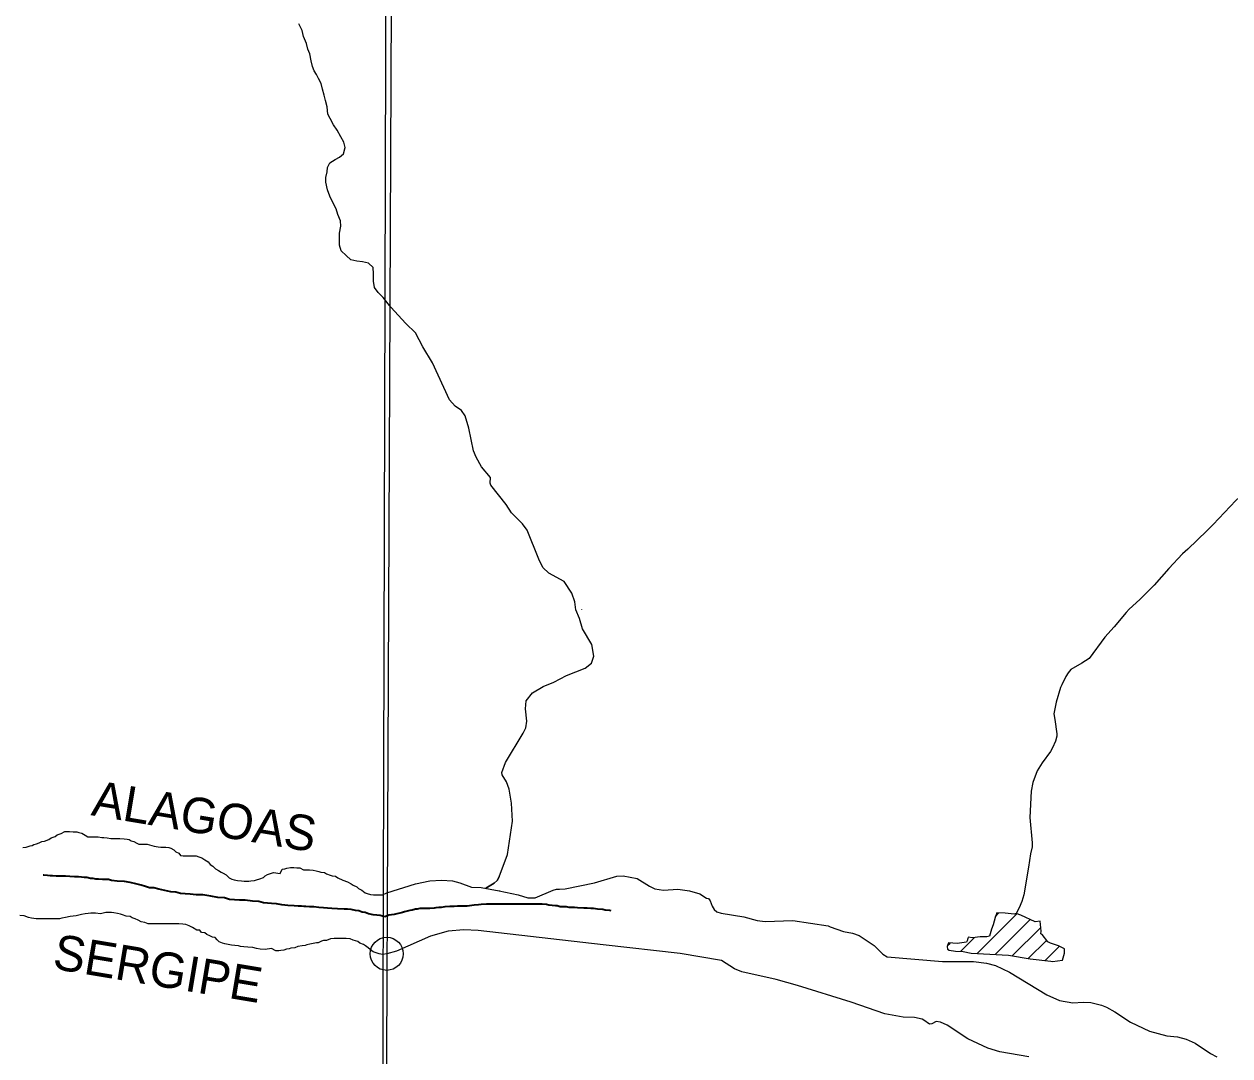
# Model space of a CAD drawing. Extents: x 553962 to 842807, y 8883888 to 9032388.
# Drawn here: x 595747 to 598478, y 8904160 to 8906496 of the extents above; entities that cross this region are included whole.
import ezdxf
from ezdxf.enums import TextEntityAlignment as Align

# ---------------------------------------------------------------- set-up
doc = ezdxf.new("R2010")
doc.units = 0
doc.header["$LTSCALE"] = 150
doc.header["$PDMODE"] = 32
doc.header["$PDSIZE"] = 75
doc.linetypes.add('LONG_DASH_SHORT_DASH', pattern=[9.9, 6, -1.2, 1.5, -1.2])
doc.layers.add('6', color=7, linetype='Continuous', lineweight=13)

msp = doc.modelspace()

# ---------------------------------------------------------------- linework, layer by layer
at = {"layer": '6'}
for p, q in [((597009.3, 8905170.6), (597009.5, 8905170.5)), ((597905.6, 8904392.3), (597995.3, 8904482)), ((597945.7, 8904390), (598025, 8904469.3)), ((597946.4, 8904475.5), (597954.7, 8904483.9)), ((597984.9, 8904386.8), (598049.1, 8904451)), ((597838.3, 8904409.9), (597844.2, 8904415.7)), ((597867.6, 8904396.8), (597899.4, 8904428.5)), ((598021.1, 8904380.5), (598062.5, 8904421.9)), ((598059, 8904376), (598091.6, 8904408.6))]:
    msp.add_line(p, q, dxfattribs=at)
for points in [[(596655.5, 8924715.8), (596593.3, 8909930.3), (596531.7, 8896026.7)], [(596461.2, 8906005.4), (596461.2, 8906022.7), (596463.8, 8906039.2), (596463.4, 8906051.2), (596457.4, 8906065.3), (596453.5, 8906078.3), (596444.6, 8906095.4), (596439.1, 8906106.9), (596433.7, 8906120.9), (596429.8, 8906138.5), (596429.8, 8906149), (596432.9, 8906162), (596433.9, 8906171.5), (596439.5, 8906182), (596451, 8906189.9), (596461, 8906195.4), (596470.1, 8906202.3), (596474.2, 8906216.8), (596471.2, 8906229.4), (596464.2, 8906241.4), (596455.8, 8906256), (596447.9, 8906268), (596439.9, 8906282.6), (596434.5, 8906292.6), (596433, 8906308.7), (596429.1, 8906323.7), (596426.2, 8906335.2), (596422.7, 8906348.8), (596419.3, 8906361.8), (596413.8, 8906373.3), (596408.8, 8906382.4), (596403.4, 8906390.9), (596399.9, 8906400.4), (596397, 8906413.4), (596393.6, 8906429), (596389.6, 8906440), (596386.2, 8906452.6), (596379.7, 8906468.6), (596376.3, 8906481.6), (596368.8, 8906497.2)], [(596838.8, 8905408.9), (596804, 8905452.2), (596802.6, 8905456.8), (596803.3, 8905469.9), (596782.8, 8905493.9), (596770.6, 8905515.5), (596764.7, 8905530.2), (596754.3, 8905581.4), (596745.9, 8905609.6), (596737.4, 8905621.2), (596722.8, 8905631.7), (596710.6, 8905646), (596672.1, 8905729.1), (596650.2, 8905765.8), (596633.6, 8905797.4), (596611.2, 8905818.6), (596577.4, 8905855.5), (596559.7, 8905877.5), (596548.7, 8905888.6), (596540.2, 8905900.2), (596538.3, 8905914.2), (596537.9, 8905930.7), (596537.5, 8905945.2), (596527, 8905955.3), (596513.5, 8905957.9), (596500.5, 8905959.4), (596487, 8905962.5), (596476, 8905972.6), (596464.6, 8905983.1), (596461.1, 8905995.7), (596461.2, 8906005.4)], [(596792.7, 8904540.1), (596811.4, 8904551.1), (596818.4, 8904557.4), (596822.7, 8904565.5), (596841.5, 8904615.9), (596853.2, 8904691.8), (596850.7, 8904732.7), (596845.1, 8904764.5), (596839.3, 8904781), (596829.4, 8904796.5), (596828.9, 8904802.2), (596837.1, 8904824.7), (596877.1, 8904890.7), (596882.8, 8904903.4), (596885.5, 8904918), (596882.5, 8904946.3), (596884.2, 8904964.5), (596897.9, 8904982), (596922.6, 8904996.6), (596946.5, 8905006.2), (596975.3, 8905021.5), (597017.5, 8905037.8), (597031.8, 8905049.4), (597037, 8905065), (597032.3, 8905091.9), (597011.4, 8905127.4), (597004.9, 8905150.7), (596996.7, 8905170.4), (596994.1, 8905188.6), (596987.3, 8905208), (596969.8, 8905234), (596935.4, 8905253.2), (596921.5, 8905266.1), (596912.2, 8905285.1), (596886, 8905350.5), (596875.4, 8905364.7), (596850.4, 8905390), (596838.8, 8905408.9)], [(595744.1, 8904632.1), (595751.7, 8904633.1), (595756.2, 8904634.6), (595760.7, 8904636), (595765.2, 8904637), (595769.2, 8904639), (595774.7, 8904640.4), (595781.2, 8904642.4), (595786.8, 8904645.4), (595793.3, 8904646.3), (595802.8, 8904650.3), (595807.8, 8904653.7), (595816.9, 8904657.2), (595821.4, 8904660.7), (595830.4, 8904663.6), (595839, 8904668.1), (595845, 8904668), (595850, 8904668), (595858, 8904667.9), (595866, 8904667.4), (595870.5, 8904665.8), (595877.5, 8904664.8), (595884.9, 8904659.7), (595891.4, 8904656.2), (595899.4, 8904656.1), (595903.4, 8904656.1), (595910.9, 8904656.1), (595914.9, 8904656), (595922.9, 8904655), (595927.4, 8904654.4), (595934.9, 8904653.9), (595943.4, 8904652.3), (595951.4, 8904652.3), (595956.4, 8904652.3), (595963.4, 8904652.2), (595973.4, 8904651.6), (595980.4, 8904651.1), (595984.9, 8904650.6), (595989.4, 8904647.5), (595995.3, 8904646), (596002.3, 8904641.9), (596006.8, 8904639.9), (596012.8, 8904639.9), (596025.8, 8904639.8), (596041.3, 8904635.2), (596045.8, 8904634.6), (596050.3, 8904633.6), (596056.3, 8904633.1), (596063.8, 8904633), (596067.8, 8904633), (596074.3, 8904632.4), (596079.3, 8904630.4), (596086.2, 8904626.9), (596090.2, 8904622.3), (596097.2, 8904619.3), (596100.7, 8904614.2), (596107.2, 8904613.2), (596113.7, 8904613.2), (596120.7, 8904613.1), (596124.7, 8904613.1), (596128.7, 8904613.1), (596136.2, 8904613), (596142.2, 8904611), (596149.6, 8904608.4), (596156.1, 8904604.4), (596163.6, 8904599.3), (596168, 8904593.3), (596174.5, 8904590.2), (596180.5, 8904583.7), (596186.9, 8904580.1), (596193.4, 8904576.1), (596197.9, 8904574.1), (596204.4, 8904570), (596211.3, 8904563.4), (596217.3, 8904560.4), (596222.8, 8904558.9), (596229.8, 8904557.3), (596238.8, 8904556.3), (596245.3, 8904556.2), (596249.3, 8904556.2), (596255.8, 8904556.1), (596260.3, 8904556.6), (596268.3, 8904557.6), (596272.8, 8904559), (596280.8, 8904561), (596288.9, 8904564.4), (596292.9, 8904567.9), (596298.4, 8904570.9), (596307, 8904574.3), (596312, 8904575.3), (596327, 8904573.2), (596331.5, 8904582.7), (596337.5, 8904584.1)], [(596337.5, 8904584.1), (596341.6, 8904585.6), (596350.1, 8904586.6), (596357.6, 8904586.5), (596364.6, 8904586), (596371.1, 8904585.9), (596379.5, 8904581.9), (596386.5, 8904581.3), (596393.5, 8904581.3), (596401.5, 8904580.7), (596408, 8904579.2), (596414, 8904578.1), (596419, 8904576.6), (596427, 8904575.5), (596432, 8904572.5), (596440, 8904569.4), (596444.5, 8904567.9), (596452, 8904566.9), (596457.4, 8904563.3), (596468.4, 8904558.2), (596478.9, 8904554.7), (596487.3, 8904550.1), (596492.3, 8904546.6), (596500.3, 8904543), (596504.3, 8904539), (596511.7, 8904535.4), (596519.2, 8904529.4), (596523.7, 8904527.8), (596531.7, 8904525.8), (596538.2, 8904524.7), (596545.2, 8904524.7), (596549.2, 8904524.7), (596554.2, 8904525.1), (596558.2, 8904525.1), (596568.1, 8904529.4), (596633, 8904549.7), (596665.5, 8904556.5), (596692.3, 8904558.4), (596717.2, 8904557), (596733.8, 8904552.4)], [(596733.8, 8904552.4), (596760.4, 8904542.1), (596781.9, 8904541.7), (596822.9, 8904534.3)], [(596822.7, 8904565.5), (596818.4, 8904557.4), (596811.4, 8904551.1), (596792.7, 8904540.1)], [(596823.3, 8904534.6), (596822.9, 8904534.3), (596866.1, 8904524.6), (596887.5, 8904518.1), (596904.4, 8904518.5), (596944.7, 8904535.2), (596952.2, 8904537.4), (596959.2, 8904537.7), (596972.2, 8904538.7), (597038.5, 8904552.3), (597088.9, 8904566.9), (597103.5, 8904567.8), (597135.1, 8904562.2), (597163.3, 8904544.4), (597175.5, 8904538.6), (597195.2, 8904535.8), (597227.3, 8904537.4), (597253.9, 8904534.1), (597277.1, 8904527.3), (597291.9, 8904517.4), (597296.9, 8904516.7), (597300.6, 8904511.3), (597305.1, 8904499.1), (597310, 8904491.8), (597315.9, 8904486.6), (597325.4, 8904483.2), (597377.2, 8904474.8), (597406.8, 8904466.6), (597425.4, 8904464.6), (597488, 8904467), (597567.9, 8904454.9)], [(596113, 8904457.9), (596106, 8904458.5), (596097.5, 8904459.1), (596092.5, 8904459.1), (596084.5, 8904459.1), (596079.5, 8904459.2), (596067.5, 8904459.2), (596057, 8904459.3), (596050, 8904459.4), (596042, 8904459.4), (596036.5, 8904459.5), (596028, 8904459.5), (596020, 8904462.6), (596012, 8904463.6), (596005, 8904467.7), (595998.5, 8904470.7), (595991.5, 8904472.8), (595987.1, 8904475.8), (595977.6, 8904476.9), (595969.6, 8904479.9), (595965.1, 8904481.5), (595958.6, 8904482.5), (595950.1, 8904484.1), (595945.1, 8904485.1), (595936.6, 8904485.2), (595932.1, 8904485.2), (595920.1, 8904482.3), (595908.6, 8904483.3), (595897.6, 8904483.4), (595892.1, 8904482.9), (595885.1, 8904482), (595877, 8904480.5), (595865, 8904477.1), (595851, 8904476.2), (595840.5, 8904473.3), (595832.5, 8904471.8), (595827, 8904470.9), (595816.4, 8904470.4), (595808.4, 8904470.5), (595798.4, 8904470.5), (595789.4, 8904470.6), (595783.9, 8904470.6), (595773.9, 8904470.7), (595763.9, 8904472.3), (595756.9, 8904473.8), (595747, 8904477.4), (595737, 8904478)], [(596137.9, 8904445.3), (596128.4, 8904450.8), (596120.5, 8904454.9), (596113, 8904457.9)], [(596412.8, 8904415.9), (596408.8, 8904415.9), (596401.3, 8904414.5), (596394.3, 8904413), (596387.2, 8904411.6), (596383.2, 8904410.6), (596376.2, 8904409.6), (596366.7, 8904408.2), (596360.2, 8904405.2), (596351.2, 8904404.3), (596347.2, 8904402.8), (596341.2, 8904401.9), (596335.1, 8904399.9), (596328.6, 8904398.9), (596324.1, 8904398.5), (596317.1, 8904398.5), (596307.2, 8904403.6), (596293.1, 8904401.2), (596281.1, 8904402.3), (596273.1, 8904403.8), (596264.6, 8904405.4), (596253.7, 8904406.4), (596244.7, 8904407.5), (596236.7, 8904408.1), (596232.2, 8904409.1), (596224.2, 8904410.2), (596216.7, 8904411.2), (596208.7, 8904412.8), (596201.2, 8904414.3), (596196.2, 8904415.8), (596188.7, 8904418.9), (596184.2, 8904422.9), (596179.3, 8904428), (596173.3, 8904429), (596167.8, 8904432.1), (596160.3, 8904435.1), (596155.8, 8904438.6), (596148.8, 8904439.7), (596144.9, 8904444.7), (596137.9, 8904445.3)], [(597784.5, 8904240.9), (597780.8, 8904243.5), (597763, 8904246.9), (597737.7, 8904248), (597696.4, 8904255.7), (597619.9, 8904282.1), (597498.2, 8904319.6), (597450, 8904332.9), (597372.6, 8904350.3), (597356, 8904357.7), (597326.5, 8904376.3), (597232.9, 8904391.8), (597058.1, 8904411.6), (596775.1, 8904444.1), (596742.4, 8904446), (596707.5, 8904442.8), (596667.4, 8904431.6), (596590.1, 8904397.6), (596568.1, 8904391.5), (596558.7, 8904389.9), (596551.2, 8904391.5), (596544.2, 8904394), (596537.7, 8904395.6), (596530.7, 8904401.1), (596526.2, 8904404.6), (596520.3, 8904409.2), (596515.8, 8904412.2), (596506.8, 8904415.8), (596502.3, 8904419.3), (596492.4, 8904422.4), (596485.4, 8904425.4), (596475.9, 8904426), (596467.4, 8904426.1), (596458.4, 8904426.1), (596449.4, 8904426.2), (596440.4, 8904425.2), (596431.8, 8904421.3), (596424.8, 8904421.3), (596420.3, 8904419.9), (596412.8, 8904415.9)], [(597567.9, 8904454.9), (597572.2, 8904452.6), (597602.6, 8904441.6), (597622.9, 8904438.2), (597638, 8904432.9), (597672.2, 8904410.2), (597691.4, 8904390.6), (597701.7, 8904384.3), (597826.9, 8904374.3), (597896.6, 8904373.8), (597926.2, 8904370), (597946.7, 8904364.9), (597978.4, 8904349.8), (598062.8, 8904298.6), (598092.1, 8904285.4), (598121.7, 8904280.6), (598145.7, 8904281.8), (598162.6, 8904280.9), (598187.1, 8904274.8), (598198.3, 8904270.4), (598217.2, 8904259.9), (598252.8, 8904236.5), (598295.7, 8904216.1), (598334.6, 8904205.9), (598358.9, 8904203.3), (598378.5, 8904198.1), (598398.6, 8904189.3), (598434, 8904165.6), (598448.2, 8904158.3)], [(598021.9, 8904158.5), (597956.3, 8904169.2), (597929.3, 8904177.5), (597883.8, 8904198.6), (597837.6, 8904229.6), (597822.4, 8904236.9), (597812.2, 8904237.9), (597802.9, 8904232.5), (597797.6, 8904231.9), (597784.5, 8904240.9)]]:
    msp.add_lwpolyline(points, dxfattribs=at)
for points in [[(596575.8, 8909932.4), (585614.8, 8909969.8), (585583.8, 8898914.4), (596544.8, 8898874.9)], [(598076.1, 8904374.3), (598098.6, 8904377.3), (598102.8, 8904393.2), (598103.1, 8904402.4), (598089.5, 8904409.8), (598071, 8904415.8), (598065, 8904418.6), (598052.1, 8904435.2), (598049.2, 8904436.8), (598050, 8904442.7), (598047.6, 8904465), (598036.8, 8904463.8), (598004.4, 8904478.8), (597993.7, 8904482.5), (597989.2, 8904480.8), (597968.7, 8904483.6), (597949.6, 8904484), (597945.8, 8904474), (597941.6, 8904457.1), (597937.6, 8904447), (597933.3, 8904431.5), (597927.5, 8904429.7), (597912, 8904430), (597894.4, 8904427.9), (597885.2, 8904428.9), (597883.8, 8904426.4), (597882.9, 8904420.8), (597881.3, 8904418.1), (597859.9, 8904414.8), (597840.3, 8904416), (597837.6, 8904407.7), (597838.4, 8904401.7), (597841.9, 8904400), (597856, 8904397.5), (597873.8, 8904396.3), (597891.4, 8904393.1), (597976.5, 8904388.3), (598025.4, 8904379.8), (598072.1, 8904374.5)]]:
    msp.add_lwpolyline(points, close=True, dxfattribs=at)
at = {"layer": '6', "lineweight": 25}
for points in [[(598811.5, 8905757.4), (598733.5, 8905676.3), (598498.6, 8905424.2), (598490.9, 8905418), (598439.8, 8905363.3), (598425.4, 8905349.3)], [(598425.4, 8905349.3), (598382.1, 8905307.4), (598370, 8905296.7), (598339.1, 8905264), (598305.9, 8905226), (598273.9, 8905193.3), (598249.7, 8905171.9), (598243, 8905164.1)], [(598243, 8905164.1), (598215.7, 8905131.8), (598194.5, 8905108.4), (598159.2, 8905060.4), (598142.4, 8905049.3), (598117.3, 8905035), (598111.1, 8905027.6), (598105.9, 8905019.5), (598097.1, 8905000.6)], [(598097.1, 8905000.6), (598094.2, 8904994.3), (598084, 8904960.9), (598079.1, 8904934.7), (598081, 8904921.7)], [(598081, 8904921.7), (598085.6, 8904889.7), (598085.6, 8904884.2), (598082.7, 8904873.1), (598076, 8904857.5), (598071.3, 8904849.5), (598052.2, 8904824.1), (598041.5, 8904805.9), (598031.7, 8904779.5), (598027.3, 8904760), (598024.5, 8904700), (598029.9, 8904642.3), (598029.5, 8904633.9), (598026.3, 8904618.1), (598021.2, 8904587.6)], [(598021.2, 8904587.6), (598010.6, 8904524.8), (598006.1, 8904509.6), (598000.4, 8904495.6), (597993.4, 8904482.7)]]:
    msp.add_lwpolyline(points, dxfattribs=at)
at = {"layer": '6', "linetype": 'LONG_DASH_SHORT_DASH', "lineweight": 35}
for points in [[(596403.1, 8904497.6), (596393.1, 8904498.1), (596385.2, 8904498.7), (596380.2, 8904498.7), (596375.2, 8904499.2), (596367.2, 8904499.3), (596358.7, 8904499.8), (596344.2, 8904500.9), (596330.2, 8904502), (596318.2, 8904504.5), (596307.2, 8904505.1), (596298.2, 8904506.1), (596288.7, 8904507.2), (596278.2, 8904509.8), (596264.2, 8904510.3), (596247.2, 8904512.9), (596234.7, 8904513), (596223.2, 8904513.5), (596212.2, 8904514.6), (596200.3, 8904518.2), (596185.3, 8904519.2), (596169.8, 8904521.8), (596151.3, 8904524.9), (596136.3, 8904525), (596122.8, 8904526.1), (596111.8, 8904527.1), (596101.3, 8904528.2), (596090.4, 8904531.3), (596079.4, 8904531.8), (596065.9, 8904534.4), (596051.9, 8904538), (596040.4, 8904540.5), (596030.9, 8904541.1), (596021.4, 8904543.6), (596012, 8904546.7), (596000, 8904549.8), (595987, 8904552.8), (595974.5, 8904555.4), (595957.5, 8904556), (595944.5, 8904557.1), (595937.6, 8904559.6), (595929.5, 8904559.6), (595924, 8904559.7), (595915.6, 8904560.2), (595909.6, 8904560.7), (595903.1, 8904561.8), (595897.1, 8904562.3), (595889.1, 8904563.9), (595883.1, 8904564.4), (595877.1, 8904564.9), (595870.1, 8904566), (595860.6, 8904566), (595850.1, 8904566.6), (595840.6, 8904567.1), (595830.1, 8904567.2), (595819.1, 8904567.2), (595811.1, 8904567.8), (595805.6, 8904567.8), (595800.1, 8904568.8), (595791.6, 8904569.4), (595790.2, 8904569.7)], [(596573, 8904478.7), (596564, 8904475.2), (596553, 8904478.3), (596546, 8904478.8), (596537, 8904479.3), (596527, 8904481.9), (596519.6, 8904484.9), (596512.1, 8904486), (596504.6, 8904488.5), (596497.1, 8904489.6), (596487.6, 8904492.1), (596479.1, 8904492.2), (596471.6, 8904492.7), (596456.6, 8904493.3), (596443.6, 8904493.9), (596434.1, 8904494.9), (596425.1, 8904495.5), (596414.6, 8904496.5), (596403.1, 8904497.6)], [(597057.4, 8904492), (597045.7, 8904492.5), (597036, 8904494), (597030.4, 8904494), (597021.8, 8904494.5), (597014.2, 8904494.5), (597000.4, 8904495.6), (596993.3, 8904496.1), (596981.1, 8904496.6), (596975, 8904497.6), (596965.8, 8904498.1), (596961.2, 8904498.1), (596954.1, 8904499.7), (596950, 8904500.2), (596942.9, 8904500.7), (596935.3, 8904501.7), (596929.7, 8904502.7), (596920, 8904503.7), (596907.3, 8904503.7), (596895.6, 8904503.7), (596890, 8904503.7), (596880.3, 8904503.7), (596874.2, 8904503.7), (596857.9, 8904503.7), (596850.8, 8904503.7), (596839.1, 8904503.7), (596833, 8904503.7), (596821.8, 8904503.7), (596815.7, 8904503.7), (596801.4, 8904503.7), (596793.8, 8904503.7), (596782.1, 8904502.7), (596776, 8904502.2), (596765.8, 8904501.7), (596760.7, 8904500.7), (596750.6, 8904499.6), (596741.9, 8904499.6), (596737.3, 8904499.6), (596728.7, 8904499.6), (596720.5, 8904498.6), (596710.8, 8904498.6), (596699.7, 8904498.1), (596691, 8904496.6), (596686.4, 8904496.1), (596679.3, 8904495.6), (596675.2, 8904494.5), (596665.6, 8904494), (596659.5, 8904494), (596654.4, 8904494), (596648.8, 8904494), (596642.7, 8904494), (596637.1, 8904492.5), (596633, 8904492.5), (596625.9, 8904490.4), (596620.3, 8904489.4), (596614.7, 8904487.9), (596608.6, 8904486.3), (596603.5, 8904484.8), (596597.4, 8904483.8), (596591.3, 8904482.3), (596585.2, 8904480.7), (596579.1, 8904479.7), (596573, 8904478.7), (596573, 8904478.7), (596573, 8904478.7)], [(597076.6, 8904488.8), (597073.7, 8904489.4), (597063, 8904490.4), (597057.4, 8904492)]]:
    msp.add_lwpolyline(points, dxfattribs=at)
at = {"layer": '6'}
msp.add_point((596568.1, 8904391.5), dxfattribs=at)

# ---------------------------------------------------------------- texts
for s, p in [('ALAGOAS', (596148.9, 8904663.4)), ('SERGIPE', (596043.6, 8904319))]:
    msp.add_text(s, height=80, rotation=350.533, dxfattribs=at).set_placement(p, align=Align.CENTER)

doc.saveas('drawing.dxf')
